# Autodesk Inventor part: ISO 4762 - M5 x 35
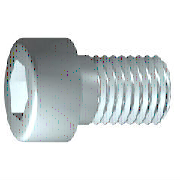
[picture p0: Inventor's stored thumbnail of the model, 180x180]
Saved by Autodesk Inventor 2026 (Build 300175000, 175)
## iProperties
IsCustomPart: 1
Created: 2022-02
Part Number: ISO 4762 - M5 x 35
Material: Steel, Mild
Description: Hexagon Socket Head Cap Screw
Document SubType Name: Modeling
Standard: ISO 4762
Designer: Lars Bertram Pedersen
Standard Revision: Fourth edition 2004-03-01
Standards Organization: ISO
Language: en-US
Size Designation: M5 x 35
Categories: <MemberInstance><Categories><Category DisplayName="Fasteners" InternalName="e4da775c-781d-43d5-af7c-5136215cf5a6" Mnemonic="FSTN"><Category DisplayName="Bolts"
Density: 7.85 g/cm^3
Appearance: Silver
Mass: 7.2686 g
Surface Area: 8.23857 cm^2
Volume: 0.925936 cm^3
Stock Number: Lager
Author: Lars Bertram Pedersen
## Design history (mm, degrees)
body "Solid1"
workplane "Work Plane1"
fillet "Fillet2" dims "d30" = 0.1 (= R)
revolve "Body" stored, may be unused: angle "d10" = 90 deg
sketch "Sketch2"
  geometry: L1 (0, -5.95)-(0, 5.95) reference; L2 (-5.95, 0)-(5.95, 0) reference; L3 (2.309, 0)-(1.155, -2); L4 (1.155, -2)-(-1.155, -2); L5 (-1.155, -2)-(-2.309, 0); L6 (-2.309, 0)-(-1.155, 2); L7 (-1.155, 2)-(1.155, 2); L8 (1.155, 2)-(2.309, 0); 2 further points
  constraints: 12 end point, 1 coincident, 1 horizontal alignment, 1 point on line, 12 other
extrude "Slot" join sketch "Sketch2" stored distance "d11" = 10; taper "d12" = 0 deg
fillet "Fillet1" dims "d17" = 0.5 (= RR)
feature "Thread" dims "d13" = 22 (= GEL), "d14" = 0
chamfer "Chamfer1" distance "d15" = 0.49076 (= -0.5 x SPD + 0.5 x GD); stored, may be unused: second distance "d16" = 0.49076 (= GUL), angle "d27" = 45 deg
sketch "Sketch1"
  geometry: L1 (-1.167, 0)-(35, 0); L2 (35, 0)-(35, 2.5); L3 (35, 2.5)-(13, 2.5); L4 (13, 2.5)-(12.509, 2.5); L5 (12.509, 2.5)-(0, 2.5); L6 (0, 2.5)-(0, 4.25); L7 (0, 4.25)-(-5, 4.25); L8 (-5, 4.25)-(-5, 2.309); L9 (-5, 2.309)-(-2.5, 2.309); L10 (-2.5, 2.309)-(-1.167, 0); L11 (-13, 0)-(43, 0) reference; L12 (0, -0.85)-(0, 5.1) reference; L13 (13, 2.5)-(0, 2.5)
  constraints: 22 end point, 6 parallel, 2 collinear, 2 perpendicular, 1 horizontal, 1 point on line
  dimensions: "d1" = 22 distance from line of L3.end L2 (= GEL); "d2" = 0.49086 distance of L4.end L3.end (computed from GAL); "d3" = 5 distance between parallel lines of L8 L6 (= KOH); "d4" = 2.5 distance of L8.end L9.end (= INTI); "d5" = 60 deg angle of L10 L1; "d6" = 5 diameter of L3 L1 (= GD); "d7" = 5 diameter of L5 L1 (= BDM); "d8" = 4.6188 diameter of L9 L1 (= 1.1547 x SW); "d9" = 8.5 diameter of L7 L1 (= KOD); "d26" = 35 distance between parallel lines of L12 L2 (= NLG)
other parameters: "GD" = 5 [user parameter; used in 2 equation terms], "NLG" = 35 [user parameter; used in 1 equation term], "GEL" = 22 [user parameter; used in 2 equation terms], "KOD" = 8.5 [user parameter; used in 1 equation term], "KOH" = 5 [user parameter; used in 1 equation term], "INTI" = 2.5 [user parameter; used in 1 equation term], "GAL" = 0.49076 (= 0.61345 x PTC) [user parameter; used in 1 equation term], "GUL" = 0.49076 (= 0.61345 x PTC) [user parameter; used in 1 equation term], "BDM" = 5 (= NND) [user parameter; used in 1 equation term], "SW" = 4 [user parameter; used in 2 equation terms], "RR" = 0.5 [user parameter; used in 1 equation term], "SPD" = 4.01848 (= NND - 1.2269 x PTC) [user parameter; used in 1 equation term], "d19" = 0, "d28" = 0, "d29" = 0, "R" = 0.1 [user parameter; used in 1 equation term], "TOA" = 30 deg [user parameter], "GD1" = 4.01848 (= THREADDIA - 1.2269 x PTC) [user parameter], "THREADDIA" = 5 [user parameter; used in 1 equation term], "FAWI" = 45 deg [user parameter], "TPU" = 12.5 (computed from PTC) [user parameter], "PTC" = 0.8 [user parameter; used in 5 equation terms], "NND" = 5 [user parameter; used in 2 equation terms], "E0" = 4.62 (= 1.155 x SW) [user parameter]
